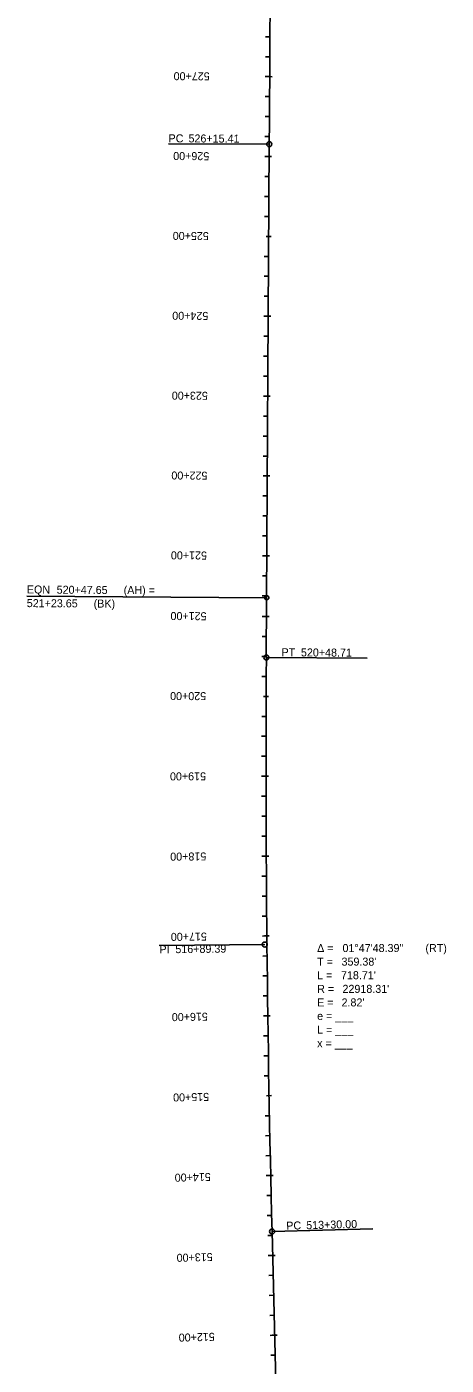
# Model space of a CAD drawing. Extents: x 23417911 to 23421158, y 6737892 to 6791804.
# Drawn here: x 23420588 to 23421112, y 6776657 to 6778333 of the extents above; entities that cross this region are included whole.
import ezdxf

# ---------------------------------------------------------------- set-up
doc = ezdxf.new("R2010")
doc.units = 0
for name, color, linetype in [('Alignment', 7, 'Continuous'), ('TextAlignment', 7, 'Continuous'), ('TextAlignmentLrg', 7, 'Continuous'), ('TextAlignmentSml', 7, 'Continuous')]:
    doc.layers.add(name, color=color, linetype=linetype)

msp = doc.modelspace()

# ---------------------------------------------------------------- linework, layer by layer
at = {"layer": 'Alignment'}
for p, q in [((23420887.2, 6777543), (23420890.9, 6778185.7)), ((23420887.2, 6777543), (23420890.9, 6778185.7)), ((23420933.8, 6775283.3), (23420894.4, 6776824.3)), ((23420933.8, 6775283.3), (23420894.4, 6776824.3))]:
    msp.add_line(p, q, dxfattribs=at)
for centre, radius, start, end in [((23293569.1, 6778919.3), 127324, 359.669872, 0.472573), ((23293569.1, 6778919.3), 127324, 359.669872, 0.472573), ((23443805.2, 6777410.9), 22918.3, 179.66987, 181.46665), ((23443805.2, 6777410.9), 22918.3, 179.66987, 181.46665)]:
    msp.add_arc(centre, radius, start, end, dxfattribs=at)
at = {"layer": 'TextAlignment'}
for p, q in [((23420890.9, 6778185.7), (23420764.9, 6778186.4)), ((23420764.9, 6778186.4), (23420764.9, 6778186.4)), ((23420887.7, 6777617.9), (23420587.7, 6777619.7)), ((23420887.2, 6777543), (23421013.2, 6777542.3)), ((23421013.2, 6777542.3), (23421013.2, 6777542.3)), ((23420885.2, 6777183.6), (23420753.2, 6777182.3)), ((23420753.2, 6777182.3), (23420753.2, 6777182.3)), ((23420894.4, 6776824.3), (23421020.3, 6776827.6)), ((23421020.3, 6776827.6), (23421020.3, 6776827.6))]:
    msp.add_line(p, q, dxfattribs=at)
for centre, radius in [((23420890.9, 6778185.7), 3.12), ((23420887.7, 6777617.9), 2.67), ((23420887.2, 6777543), 3.12), ((23420885.2, 6777183.6), 3.12), ((23420894.4, 6776824.3), 3.12)]:
    msp.add_circle(centre, radius, dxfattribs=at)
at = {"layer": 'TextAlignmentLrg'}
for p, q in [((23420891.4, 6778270.3), (23420885.9, 6778270.3)), ((23420890.8, 6778170.3), (23420885.4, 6778170.3)), ((23420887.2, 6778070.3), (23420893.3, 6778070.2)), ((23420889.7, 6777970.3), (23420884.2, 6777970.3)), ((23420889.1, 6777870.3), (23420883.6, 6777870.3)), ((23420888.5, 6777770.3), (23420883.1, 6777770.3)), ((23420888, 6777670.3), (23420882.5, 6777670.3)), ((23420887.5, 6777594.3), (23420882.1, 6777594.3)), ((23420883.9, 6777494.3), (23420890.1, 6777494.3)), ((23420886.8, 6777394.3), (23420881.4, 6777394.3)), ((23420887.1, 6777294.3), (23420881.7, 6777294.2)), ((23420887.9, 6777194.3), (23420882.4, 6777194.2)), ((23420889, 6777094.3), (23420883.6, 6777094.2)), ((23420887.6, 6776994.2), (23420893.7, 6776994.4)), ((23420892.7, 6776894.3), (23420887.2, 6776894.2)), ((23420895.1, 6776794.4), (23420889.7, 6776794.2)), ((23420897.7, 6776694.4), (23420892.2, 6776694.2))]:
    msp.add_line(p, q, dxfattribs=at)
at = {"layer": 'TextAlignmentSml'}
for p, q in [((23420891.6, 6778320.3), (23420886.2, 6778320.3)), ((23420891.5, 6778295.3), (23420886.1, 6778295.3)), ((23420888.3, 6778270.3), (23420894.4, 6778270.2)), ((23420891.3, 6778245.3), (23420885.8, 6778245.3)), ((23420891.1, 6778220.3), (23420885.7, 6778220.3)), ((23420891, 6778195.3), (23420885.5, 6778195.3)), ((23420887.8, 6778170.3), (23420893.9, 6778170.2)), ((23420890.7, 6778145.3), (23420885.2, 6778145.3)), ((23420890.5, 6778120.3), (23420885.1, 6778120.3)), ((23420890.4, 6778095.3), (23420884.9, 6778095.3)), ((23420887.2, 6778070.3), (23420893.3, 6778070.2)), ((23420890.1, 6778045.3), (23420884.7, 6778045.3)), ((23420890, 6778020.3), (23420884.5, 6778020.3)), ((23420889.8, 6777995.3), (23420884.4, 6777995.3)), ((23420886.6, 6777970.3), (23420892.7, 6777970.3)), ((23420889.5, 6777945.3), (23420884.1, 6777945.3)), ((23420889.4, 6777920.3), (23420883.9, 6777920.3)), ((23420889.3, 6777895.3), (23420883.8, 6777895.3)), ((23420886, 6777870.3), (23420892.2, 6777870.3)), ((23420889, 6777845.3), (23420883.5, 6777845.3)), ((23420888.8, 6777820.3), (23420883.4, 6777820.3)), ((23420888.7, 6777795.3), (23420883.2, 6777795.3)), ((23420885.5, 6777770.3), (23420891.6, 6777770.3)), ((23420888.4, 6777745.3), (23420882.9, 6777745.3)), ((23420888.2, 6777720.3), (23420882.8, 6777720.3)), ((23420888.1, 6777695.3), (23420882.6, 6777695.3)), ((23420884.9, 6777670.3), (23420891, 6777670.3)), ((23420887.8, 6777645.3), (23420882.4, 6777645.3)), ((23420887.7, 6777620.3), (23420882.2, 6777620.3)), ((23420884.5, 6777594.3), (23420890.6, 6777594.3)), ((23420887.4, 6777569.3), (23420881.9, 6777569.3)), ((23420887.2, 6777544.3), (23420881.8, 6777544.3)), ((23420887.1, 6777519.3), (23420881.6, 6777519.3)), ((23420883.9, 6777494.3), (23420890.1, 6777494.3)), ((23420886.9, 6777469.3), (23420881.5, 6777469.3)), ((23420886.9, 6777444.3), (23420881.4, 6777444.3)), ((23420886.8, 6777419.3), (23420881.4, 6777419.3)), ((23420883.8, 6777394.3), (23420889.9, 6777394.3)), ((23420886.9, 6777369.3), (23420881.4, 6777369.3)), ((23420886.9, 6777344.3), (23420881.5, 6777344.3)), ((23420887, 6777319.3), (23420881.6, 6777319.3)), ((23420884.1, 6777294.3), (23420890.2, 6777294.3)), ((23420887.3, 6777269.3), (23420881.8, 6777269.2)), ((23420887.4, 6777244.3), (23420882, 6777244.2)), ((23420887.6, 6777219.3), (23420882.2, 6777219.2)), ((23420884.8, 6777194.3), (23420890.9, 6777194.3)), ((23420888.1, 6777169.3), (23420882.7, 6777169.2)), ((23420888.4, 6777144.3), (23420882.9, 6777144.2)), ((23420888.7, 6777119.3), (23420883.2, 6777119.2)), ((23420886, 6777094.2), (23420892.1, 6777094.3)), ((23420889.4, 6777069.3), (23420883.9, 6777069.2)), ((23420889.8, 6777044.3), (23420884.3, 6777044.2)), ((23420890.2, 6777019.3), (23420884.7, 6777019.2)), ((23420887.6, 6776994.2), (23420893.7, 6776994.4)), ((23420891.1, 6776969.3), (23420885.6, 6776969.2)), ((23420891.6, 6776944.3), (23420886.1, 6776944.2)), ((23420892.1, 6776919.3), (23420886.7, 6776919.2)), ((23420889.6, 6776894.3), (23420895.7, 6776894.4)), ((23420893.2, 6776869.3), (23420887.8, 6776869.2)), ((23420893.8, 6776844.3), (23420888.4, 6776844.2)), ((23420894.5, 6776819.3), (23420889, 6776819.2)), ((23420892.1, 6776794.3), (23420898.2, 6776794.4)), ((23420895.8, 6776769.4), (23420890.3, 6776769.2)), ((23420896.4, 6776744.4), (23420890.9, 6776744.2)), ((23420897, 6776719.4), (23420891.6, 6776719.2)), ((23420894.6, 6776694.3), (23420900.7, 6776694.5)), ((23420898.3, 6776669.4), (23420892.9, 6776669.3))]:
    msp.add_line(p, q, dxfattribs=at)

# ---------------------------------------------------------------- texts
at = {"layer": 'TextAlignment'}
for s, rotation, p in [('PC', 359.6699, (23420764.9, 6778188.1)), ('526+15.41', 359.6699, (23420789.9, 6778188)), ('EQN ', 359.6699, (23420587.7, 6777623.2)), ('520+47.65', 359.6699, (23420625, 6777622.9)), ('(AH) = ', 359.6699, (23420708.8, 6777622.5)), ('521+23.65', 359.6699, (23420587.6, 6777606.1)), ('(BK)', 359.6699, (23420671.3, 6777605.6)), ('PT', 359.6699, (23420906.2, 6777544.6)), ('520+48.71', 359.6699, (23420930.5, 6777544.4)), ('PI ', 0.5683, (23420753.6, 6777172.6)), ('516+89.39', 0.5683, (23420773.5, 6777172.8)), ('PC', 1.4666, (23420912.3, 6776826.5)), ('513+30.00', 1.4666, (23420937.2, 6776827.1))]:
    msp.add_text(s, height=10.02, rotation=rotation, dxfattribs=at).set_placement(p)
for s, p in [('Δ = ', (23420950.8, 6777174.2)), ('01°47\'48.39"', (23420982.5, 6777174.2)), (' (RT)', (23421082.5, 6777174.2)), ('T = ', (23420950.8, 6777157.2)), ("359.38'", (23420981.3, 6777157.2)), ('L = ', (23420950.8, 6777140.2)), ("718.71'", (23420980.6, 6777140.2)), ('R = ', (23420950.8, 6777123.1)), ("22918.31'", (23420982.5, 6777123.1)), ('E = ', (23420950.8, 6777106.1)), ("2.82'", (23420981.3, 6777106.1)), ('e = ___ ', (23420950.8, 6777089.1)), ('L = ___', (23420950.8, 6777072)), ('x = ___', (23420950.8, 6777055))]:
    msp.add_text(s, height=10.02, dxfattribs=at).set_placement(p)
at = {"layer": 'TextAlignmentLrg'}
for s, rotation, p in [('525+00', 179.6699, (23420815.3, 6778075.7)), ('520+00', 179.7917, (23420812, 6777499.6)), ('515+00', 181.0417, (23420815.6, 6776997.9))]:
    msp.add_text(s, height=10.02, rotation=rotation, dxfattribs=at).set_placement(p)
at = {"layer": 'TextAlignmentSml'}
for s, rotation, p in [('527+00', 179.7079, (23420816.4, 6778275.7)), ('526+00', 179.6699, (23420815.9, 6778175.7)), ('525+00', 179.6699, (23420815.3, 6778075.7)), ('524+00', 179.6699, (23420814.7, 6777975.7)), ('523+00', 179.6699, (23420814.1, 6777875.7)), ('522+00', 179.6699, (23420813.6, 6777775.7)), ('521+00', 179.6699, (23420813, 6777675.7)), ('521+00', 179.6699, (23420812.5, 6777599.7)), ('520+00', 179.7917, (23420812, 6777499.6)), ('519+00', 180.0417, (23420811.8, 6777399.2)), ('518+00', 180.2917, (23420812.1, 6777298.9)), ('517+00', 180.5417, (23420812.8, 6777198.6)), ('516+00', 180.7917, (23420814, 6777098.3)), ('515+00', 181.0417, (23420815.6, 6776997.9)), ('514+00', 181.2917, (23420817.6, 6776897.6)), ('513+00', 181.4666, (23420820, 6776797.4)), ('512+00', 181.4666, (23420822.6, 6776697.5))]:
    msp.add_text(s, height=10.02, rotation=rotation, dxfattribs=at).set_placement(p)

doc.saveas('drawing.dxf')
